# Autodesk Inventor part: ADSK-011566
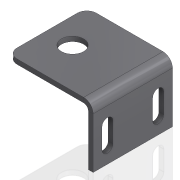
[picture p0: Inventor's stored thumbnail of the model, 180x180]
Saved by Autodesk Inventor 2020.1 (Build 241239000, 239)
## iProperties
Created: 2000-02
Part Number: ADSK-011566
Material: 1.0312 DC05
Document SubType Name: Tôlerie
Description: FSHTPH,SS,AX,01,020,013,020,090,BRKT,ROLL_MNTS
Designer: cmcgourin
Density: 1 g/cm^3
Sheet Metal Rule: Stahlblech 1.0312 - DC05 -   3.0 mm
Appearance: Metal-Steel(Polish)
Mass: 11.7962 g
Surface Area: 90.85 cm^2
Volume: 11.7962 cm^3
Flat Pattern Width: 5 cm
Flat Pattern Length: 8.67858 cm
Flat Pattern Area: 43.3929 cm^2
Sheet Metal Width: 50,000 mm
Sheet Metal Length: 86,786 mm
Sheet Metal Area: 4339,292 mm^2
Control State: 0
Checked Out: False
Master: False
Shininess: 57.0
Length Units: 11269
Angle Units: 11279
Time Units: 11290
Mass Units: 11283
Length Display Precision: 3
Angle Display Precision: 2
Compacted: True
Cutlength: (2.00 X 3.41) 7 SI
Material Desc: SHEET,SS,11GA
Material_Number: A084638
G_L: 50x86,8 mm
Thickness: 3,000 mm
Dimensions: 38x50x54 mm
Mass: 0,012 kg
Semi finished: Stahlblech 1.0312 - DC05 -   3.0 mm
VLT_Material: 1.0312 DC05
Density: 0.0
Volumn: 0.0
Area: 0.0
PropertySet Name: Model Information
Author: cmcgourin
Revision Number: -
Title: FSHTPH,SS,AX,01,020,013,020,090,BRKT,ROLL_MNTS
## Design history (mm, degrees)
node "Solide1"
  node "Konturlasche1"
sketch "Sketch1"
  geometry: L1 (0, 0)-(-51, 0); L2 (0, -35)-(0, 0); 1 further point
  constraints: 4 end point, 1 coincident, 1 horizontal, 1 perpendicular
  dimensions: "d4" = 51 distance of L1.start L1.end; "d5" = 35 distance of L2.start L1.start
sketch "Skizze9"
  geometry: L1 (9, 22)-(9, 9.5); L2 (5.5, 22)-(5.5, 9.5); L3 (12.5, 9.5)-(12.5, 22); L4 (41, 22)-(41, 9.5); L5 (37.5, 22)-(37.5, 9.5); L6 (44.5, 9.5)-(44.5, 22); L7 (9, 15.75)-(41, 15.75); L8 (50, 0)-(0, 0) reference; A1 r 3.5 centre (9, 22) between (12.5, 22) and (5.5, 22); A2 r 3.5 centre (9, 9.5) between (5.5, 9.5) and (12.5, 9.5); A3 r 3.5 centre (41, 22) between (44.5, 22) and (37.5, 22); A4 r 3.5 centre (41, 9.5) between (37.5, 9.5) and (44.5, 9.5); 3 further points
  constraints: 18 end point, 8 point on circle, 8 tangent, 4 centre point, 4 midpoint, 2 parallel, 2 vertical, 1 horizontal, 1 vertical alignment
  dimensions: "d42" = 12.5 distance of L1.start L1.end; "d43" = 7 diameter of A2; "d44" = 12.5 distance of L4.start L4.end; "d45" = 7 diameter of A4; "d46" = 32 distance of L7.start L7.end; "d48" = 9.5 distance from line of L4.end L8
feature "Ausklinkung1" sketch "Skizze9" dims "d49" = 3 (= Thickness), "d50" = 0
sketch "Skizze10"
  geometry: L1 (54, 0)-(54, 50) reference; 2 further points
  constraints: 1 horizontal alignment
  dimensions: "d51" = 38 distance from line of L1 point (16, 25)
hole "Bohrung2" sketch "Skizze10" diameter "d52" = 14; stored, may be unused: countersink angle "d56" = 90 deg, drill point angle "d58" = 118 deg; dims "d53" = 6, "d54" = 12.6, "d55" = 2, "d57" = 3 (= Thickness)
feature "Eckenrundung1" dims "d59" = 6
feature "Grobblech3" dims "d31" = 3 (= Thickness), "d32" = 3 (= BendReliefWidth), "d33" = 1.5 (= BendReliefDepth), "d34" = 6 (= MinimumRemnant), "d35" = 3 (= TransitionRadius), "d36" = 50, "d37" = 3 (= BendRadius), "d38" = 3, "d39" = 12 (= CornerReliefSize), "d40" = 3 (= TailleJeu), "d41" = 3 (= TailleRayonJacobi), "SeamGap" = 0.00508
feature "Biegung2" dims "d31" = 3 (= Thickness), "d32" = 3 (= BendReliefWidth), "d33" = 1.5 (= BendReliefDepth), "d34" = 6 (= MinimumRemnant), "d35" = 3 (= TransitionRadius), "d37" = 3 (= BendRadius), "d38" = 3, "SeamGap" = 0.00508
feature "Ecke1" dims "d38" = 3, "d39" = 12 (= CornerReliefSize), "d40" = 3 (= TailleJeu), "d41" = 3 (= TailleRayonJacobi)
node "Corps solides"
node "Corps surfaciques"
feature "Definition1"
other parameters: "Thickness" = 3 (derived), "BendRadius" = 3 (= Thickness), "BendReliefWidth" = 3 (= Thickness), "BendReliefDepth" = 1.5 (= 0.5 x Thickness), "CornerReliefSize" = 12 (= 4 x Thickness), "MinimumRemnant" = 6 (= 2 x Thickness), "d0" = 3 (= BendRadius), "TransitionRadius" = 3 (= BendRadius), "TailleRayonJacobi" = 3 (= BendRadius), "TailleJeu" = 3 (= Thickness), "BendRadius" = 3, "BendReliefDepth" = 1.5, "BendReliefWidth" = 3, "CornerReliefSize" = 12, "MinimumRemnant" = 6, "TailleJeu" = 3, "TailleRayonJacobi" = 3, "Thickness" = 3, "TransitionRadius" = 3
